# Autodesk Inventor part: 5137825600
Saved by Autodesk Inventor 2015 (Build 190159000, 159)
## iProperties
Created: 2020-07
Part Number: 5137825600
Checked By: TraceParts S.A.
Material: Generic
Catalog Web Link: www.traceparts.com
Document SubType Name: Modeling
Designer: TraceParts
Density: 1 g/cm^3
Appearance: Default
Company: TraceParts S.A.
Author: TraceParts
REFERENCE: 5137825600
DESIGN: CVAB/4-3000/355 N D 0,31KW (230V) 50Hz - 5137825600
SUPPLIER: Soler & Palau
TraceParts.PartNumber: 10-14122018-105188
TraceParts.PartTitle: CVAT-N
TraceParts.InstanceId: 10-14122018-1051888JZXX7ATQ95ZCH2DG7ZGI3RGP
TraceParts.PartStatus: Published
TraceParts.PartVersion: 1.0.4
TRACEPARTS: TRACEPARTS
TraceParts.PartLanguage: en
TraceParts.ClassPath: SOLER_PALAU:10-14122018-105188
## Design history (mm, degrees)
feature "5137825600"
body "Solid1"
